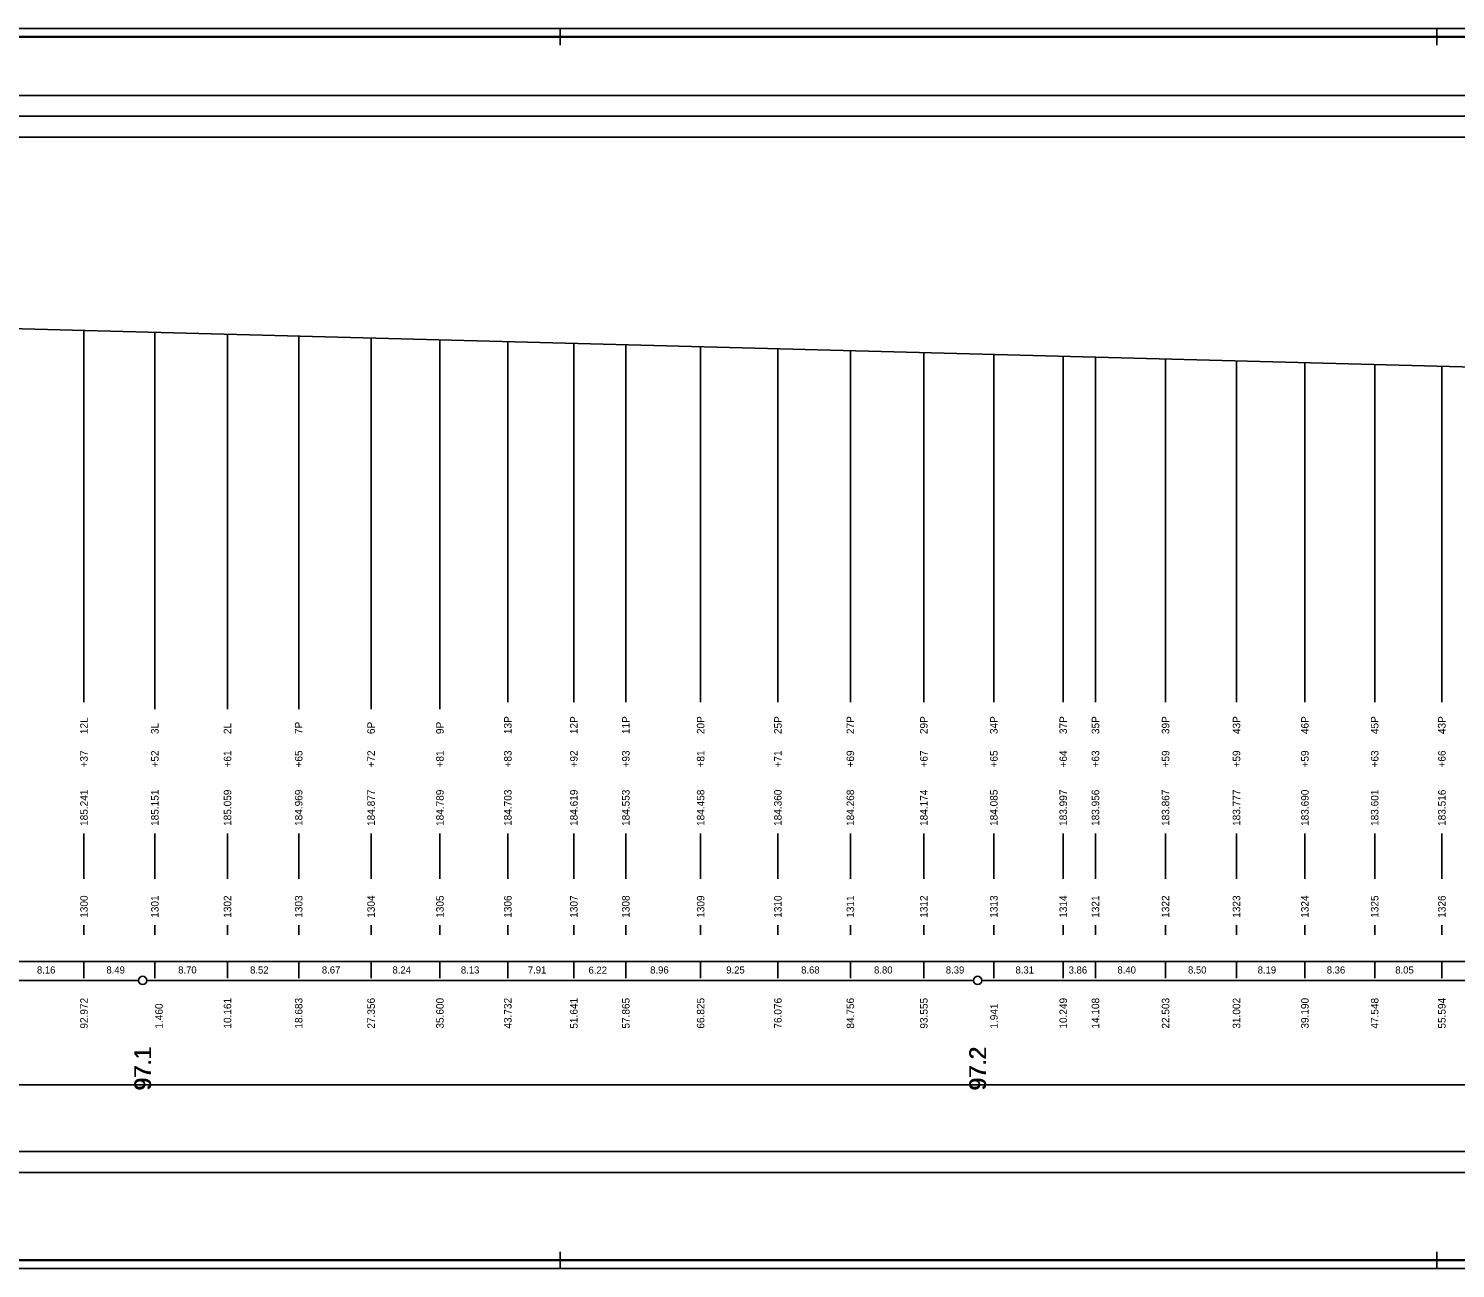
# Model space of a CAD drawing. Extents: x 0 to 10087, y -805 to 297.
# Drawn here: x 1552.7 to 1894.5, y 0 to 297 of the extents above; entities that cross this region are included whole.
import ezdxf

# ---------------------------------------------------------------- set-up
doc = ezdxf.new("R2010")
doc.units = 0
for name, color, linetype in [('CARKY_HODNOT', 7, 'Continuous'), ('KRIV1_CARA', 7, 'Continuous'), ('NIVELETA_CARA', 7, 'Continuous'), ('RAM', 7, 'Continuous'), ('REZERVA', 7, 'Continuous'), ('STAN_CARA', 7, 'Continuous'), ('STAN_PAS', 7, 'Continuous'), ('STAN_TEXT', 7, 'Continuous'), ('TEXT', 7, 'Continuous'), ('TXT_C_BODU', 7, 'Continuous')]:
    doc.layers.add(name, color=color, linetype=linetype)

msp = doc.modelspace()

# ---------------------------------------------------------------- linework, layer by layer
at = {"layer": 'CARKY_HODNOT'}
for p, q in [((1565.94, 138.35), (1565.94, 224.71)), ((1582.92, 138.35), (1582.92, 224.26)), ((1600.32, 138.35), (1600.32, 223.8)), ((1617.37, 138.35), (1617.37, 223.34)), ((1634.71, 138.35), (1634.71, 222.88)), ((1651.2, 138.35), (1651.2, 222.45)), ((1667.46, 138.35), (1667.46, 222.01)), ((1683.28, 138.35), (1683.28, 221.59)), ((1695.73, 138.35), (1695.73, 221.26)), ((1713.65, 138.35), (1713.65, 220.79)), ((1732.15, 138.35), (1732.15, 220.3)), ((1749.51, 138.35), (1749.51, 219.84)), ((1767.11, 138.35), (1767.11, 219.37)), ((1783.88, 138.35), (1783.88, 218.93)), ((1800.5, 138.35), (1800.5, 218.48)), ((1808.22, 138.35), (1808.22, 218.28)), ((1825.01, 138.35), (1825.01, 217.83)), ((1842, 138.35), (1842, 217.38)), ((1858.38, 138.35), (1858.38, 216.95)), ((1875.1, 138.35), (1875.1, 216.51)), ((1891.19, 138.35), (1891.19, 216.08)), ((1565.94, 135.65), (1565.94, 138.35)), ((1582.92, 134), (1582.92, 138.35)), ((1600.32, 134), (1600.32, 138.35)), ((1617.37, 134), (1617.37, 138.35)), ((1634.71, 134), (1634.71, 138.35)), ((1651.2, 134), (1651.2, 138.35)), ((1667.46, 135.65), (1667.46, 138.35)), ((1683.28, 135.65), (1683.28, 138.35)), ((1695.73, 135.65), (1695.73, 138.35)), ((1713.65, 135.65), (1713.65, 138.35)), ((1732.15, 135.65), (1732.15, 138.35)), ((1749.51, 135.65), (1749.51, 138.35)), ((1767.11, 135.65), (1767.11, 138.35)), ((1783.88, 135.65), (1783.88, 138.35)), ((1800.5, 135.65), (1800.5, 138.35)), ((1808.22, 135.65), (1808.22, 138.35)), ((1825.01, 135.65), (1825.01, 138.35)), ((1842, 135.65), (1842, 138.35)), ((1858.38, 135.65), (1858.38, 138.35)), ((1875.1, 135.65), (1875.1, 138.35)), ((1891.19, 135.65), (1891.19, 138.35)), ((1565.94, 93.3), (1565.94, 104.2)), ((1582.92, 93.3), (1582.92, 104.2)), ((1600.32, 93.3), (1600.32, 104.2)), ((1617.37, 93.3), (1617.37, 104.2)), ((1634.71, 93.3), (1634.71, 104.2)), ((1651.2, 93.3), (1651.2, 104.2)), ((1667.46, 93.3), (1667.46, 104.2)), ((1683.28, 93.3), (1683.28, 104.2)), ((1695.73, 93.3), (1695.73, 104.2)), ((1713.65, 93.3), (1713.65, 104.2)), ((1732.15, 93.3), (1732.15, 104.2)), ((1749.51, 93.3), (1749.51, 104.2)), ((1767.11, 93.3), (1767.11, 104.2)), ((1783.88, 93.3), (1783.88, 104.2)), ((1800.5, 93.3), (1800.5, 104.2)), ((1808.22, 93.3), (1808.22, 104.2)), ((1825.01, 93.3), (1825.01, 104.2)), ((1842, 93.3), (1842, 104.2)), ((1858.38, 93.3), (1858.38, 104.2)), ((1875.1, 93.3), (1875.1, 104.2)), ((1891.19, 93.3), (1891.19, 104.2)), ((1565.94, 79.9), (1565.94, 82.2)), ((1582.92, 79.9), (1582.92, 82.2)), ((1600.32, 79.9), (1600.32, 82.2)), ((1617.37, 79.9), (1617.37, 82.2)), ((1634.71, 79.9), (1634.71, 82.2)), ((1651.2, 79.9), (1651.2, 82.2)), ((1667.46, 79.9), (1667.46, 82.2)), ((1683.28, 79.9), (1683.28, 82.2)), ((1695.73, 79.9), (1695.73, 82.2)), ((1713.65, 79.9), (1713.65, 82.2)), ((1732.15, 79.9), (1732.15, 82.2)), ((1749.51, 79.9), (1749.51, 82.2)), ((1767.11, 79.9), (1767.11, 82.2)), ((1783.88, 79.9), (1783.88, 82.2)), ((1800.5, 79.9), (1800.5, 82.2)), ((1808.22, 79.9), (1808.22, 82.2)), ((1825.01, 79.9), (1825.01, 82.2)), ((1842, 79.9), (1842, 82.2)), ((1858.38, 79.9), (1858.38, 82.2)), ((1875.1, 79.9), (1875.1, 82.2)), ((1891.19, 79.9), (1891.19, 82.2))]:
    msp.add_line(p, q, dxfattribs=at)
at = {"layer": 'KRIV1_CARA'}
msp.add_line((1094.43, 44), (1956.46, 44), dxfattribs=at)
at = {"layer": 'NIVELETA_CARA'}
for p, q in [((300, 281), (8321.33, 281)), ((300, 276), (8321.33, 276)), ((300, 271), (8321.33, 271)), ((1498.66, 226.49), (1929.51, 215.06)), ((500, 28), (8321.33, 28)), ((500, 23), (8321.33, 23))]:
    msp.add_line(p, q, dxfattribs=at)
at = {"layer": 'RAM'}
for p, q in [((8636.33, 297), (0, 297)), ((8634.33, 295.1), (2, 295.1)), ((8634.33, 295), (2, 295)), ((8634.33, 294.9), (2, 294.9)), ((1680, 293), (1680, 297)), ((1890, 293), (1890, 297)), ((1680, 0), (1680, 4)), ((1890, 0), (1890, 4)), ((0, 0), (8636.33, 0)), ((2, 2.1), (8634.33, 2.1)), ((2, 2), (8634.33, 2)), ((2, 1.9), (8634.33, 1.9))]:
    msp.add_line(p, q, dxfattribs=at)
at = {"layer": 'REZERVA'}
for centre in [(1580, 69), (1780, 69)]:
    msp.add_circle(centre, 1, dxfattribs=at)
at = {"layer": 'STAN_CARA'}
for p, q in [((1381.5, 69), (1579, 69)), ((1581, 69), (1779, 69)), ((1781, 69), (1979, 69))]:
    msp.add_line(p, q, dxfattribs=at)
at = {"layer": 'STAN_PAS'}
for p, q in [((300, 73.5), (8321.33, 73.5)), ((1565.94, 69.5), (1565.94, 73.5)), ((1582.92, 69.5), (1582.92, 73.5)), ((1600.32, 69.5), (1600.32, 73.5)), ((1617.37, 69.5), (1617.37, 73.5)), ((1634.71, 69.5), (1634.71, 73.5)), ((1651.2, 69.5), (1651.2, 73.5)), ((1667.46, 69.5), (1667.46, 73.5)), ((1683.28, 69.5), (1683.28, 73.5)), ((1695.73, 69.5), (1695.73, 73.5)), ((1713.65, 69.5), (1713.65, 73.5)), ((1732.15, 69.5), (1732.15, 73.5)), ((1749.51, 69.5), (1749.51, 73.5)), ((1767.11, 69.5), (1767.11, 73.5)), ((1783.88, 69.5), (1783.88, 73.5)), ((1800.5, 69.5), (1800.5, 73.5)), ((1808.22, 69.5), (1808.22, 73.5)), ((1825.01, 69.5), (1825.01, 73.5)), ((1842, 69.5), (1842, 73.5)), ((1858.38, 69.5), (1858.38, 73.5)), ((1875.1, 69.5), (1875.1, 73.5)), ((1891.19, 69.5), (1891.19, 73.5))]:
    msp.add_line(p, q, dxfattribs=at)

# ---------------------------------------------------------------- texts
at = {"layer": 'STAN_TEXT'}
for s, p in [('8.16', (1554.67, 70.65)), ('8.49', (1571.32, 70.65)), ('8.70', (1588.5, 70.65)), ('8.52', (1605.73, 70.65)), ('8.67', (1622.92, 70.65)), ('8.24', (1639.84, 70.65)), ('8.13', (1656.22, 70.65)), ('7.91', (1672.26, 70.65)), ('6.22', (1686.79, 70.61)), ('8.96', (1701.57, 70.65)), ('9.25', (1719.78, 70.65)), ('8.68', (1737.72, 70.65)), ('8.80', (1755.19, 70.65)), ('8.39', (1772.38, 70.65)), ('8.31', (1789.07, 70.65)), ('3.86', (1801.8, 70.64)), ('8.40', (1813.49, 70.65)), ('8.50', (1830.39, 70.65)), ('8.19', (1847.07, 70.65)), ('8.36', (1863.62, 70.65)), ('8.05', (1880.03, 70.65))]:
    msp.add_text(s, height=1.7, dxfattribs=at).set_placement(p)
for s, height, p in [('92.972', 1.8, (1566.84, 57.45)), ('1.460', 1.8, (1584.8, 57.45)), ('10.161', 1.8, (1601.22, 57.45)), ('18.683', 1.8, (1618.27, 57.45)), ('27.356', 1.8, (1635.61, 57.45)), ('35.600', 1.8, (1652.1, 57.45)), ('43.732', 1.8, (1668.36, 57.45)), ('51.641', 1.8, (1684.18, 57.45)), ('57.865', 1.8, (1696.63, 57.45)), ('66.825', 1.8, (1714.55, 57.45)), ('76.076', 1.8, (1733.05, 57.45)), ('84.756', 1.8, (1750.41, 57.45)), ('93.555', 1.8, (1768.01, 57.45)), ('1.941', 1.8, (1784.8, 57.45)), ('10.249', 1.8, (1801.4, 57.45)), ('14.108', 1.8, (1809.12, 57.45)), ('22.503', 1.8, (1825.91, 57.45)), ('31.002', 1.8, (1842.9, 57.45)), ('39.190', 1.8, (1859.28, 57.45)), ('47.548', 1.8, (1876, 57.45)), ('55.594', 1.8, (1892.09, 57.45)), ('    97.1', 4, (1582, 36.84)), ('    97.1', 4, (1582, 36.74)), ('    97.1', 4, (1582, 36.64)), ('    97.2', 4, (1782, 36.84)), ('    97.2', 4, (1782, 36.74)), ('    97.2', 4, (1782, 36.64))]:
    msp.add_text(s, height=height, rotation=90, dxfattribs=at).set_placement(p)
at = {"layer": 'TEXT'}
for s, p in [('12L', (1566.84, 128)), ('3L', (1583.82, 128)), ('2L', (1601.22, 128)), ('7P', (1618.27, 128)), ('6P', (1635.61, 128)), ('9P', (1652.1, 128)), ('13P', (1668.36, 128)), ('12P', (1684.18, 128)), ('11P', (1696.63, 128)), ('20P', (1714.55, 128)), ('25P', (1733.05, 128)), ('27P', (1750.41, 128)), ('29P', (1768.01, 128)), ('34P', (1784.78, 128)), ('37P', (1801.4, 128)), ('35P', (1809.12, 128)), ('39P', (1825.91, 128)), ('43P', (1842.9, 128)), ('46P', (1859.28, 128)), ('45P', (1876, 128)), ('43P', (1892.09, 128)), ('+37', (1566.84, 120)), ('+52', (1583.82, 120)), ('+61', (1601.22, 120)), ('+65', (1618.27, 120)), ('+72', (1635.61, 120)), ('+81', (1652.1, 120)), ('+83', (1668.36, 120)), ('+92', (1684.18, 120)), ('+93', (1696.63, 120)), ('+81', (1714.55, 120)), ('+71', (1733.05, 120)), ('+69', (1750.41, 120)), ('+67', (1768.01, 120)), ('+65', (1784.78, 120)), ('+64', (1801.4, 120)), ('+63', (1809.12, 120)), ('+59', (1825.91, 120)), ('+59', (1842.9, 120)), ('+59', (1859.28, 120)), ('+63', (1876, 120)), ('+66', (1892.09, 120)), ('185.241', (1566.84, 106)), ('185.151', (1583.82, 106)), ('185.059', (1601.22, 106)), ('184.969', (1618.27, 106)), ('184.877', (1635.61, 106)), ('184.789', (1652.1, 106)), ('184.703', (1668.36, 106)), ('184.619', (1684.18, 106)), ('184.553', (1696.63, 106)), ('184.458', (1714.55, 106)), ('184.360', (1733.05, 106)), ('184.268', (1750.41, 106)), ('184.174', (1768.01, 106)), ('184.085', (1784.78, 106)), ('183.997', (1801.4, 106)), ('183.956', (1809.12, 106)), ('183.867', (1825.91, 106)), ('183.777', (1842.9, 106)), ('183.690', (1859.28, 106)), ('183.601', (1876, 106)), ('183.516', (1892.09, 106))]:
    msp.add_text(s, height=1.8, rotation=90, dxfattribs=at).set_placement(p)
at = {"layer": 'TXT_C_BODU'}
for s, p in [('1300', (1566.84, 84)), ('1301', (1583.82, 84)), ('1302', (1601.22, 84)), ('1303', (1618.27, 84)), ('1304', (1635.61, 84)), ('1305', (1652.1, 84)), ('1306', (1668.36, 84)), ('1307', (1684.18, 84)), ('1308', (1696.63, 84)), ('1309', (1714.55, 84)), ('1310', (1733.05, 84)), ('1311', (1750.41, 84)), ('1312', (1768.01, 84)), ('1313', (1784.78, 84)), ('1314', (1801.4, 84)), ('1321', (1809.12, 84)), ('1322', (1825.91, 84)), ('1323', (1842.9, 84)), ('1324', (1859.28, 84)), ('1325', (1876, 84)), ('1326', (1892.09, 84))]:
    msp.add_text(s, height=1.8, rotation=90, dxfattribs=at).set_placement(p)

doc.saveas('drawing.dxf')
